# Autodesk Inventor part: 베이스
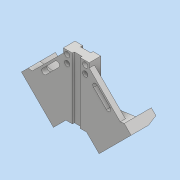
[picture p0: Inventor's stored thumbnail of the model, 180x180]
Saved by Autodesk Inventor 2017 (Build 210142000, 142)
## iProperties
Part Number: 베이스
Material: 일반
Document SubType Name: Modeling
Designer: mrc
Density: 1 g/cm^3
Appearance: 기본값
Mass: 211.682 g
Surface Area: 407.272 cm^2
Volume: 211.682 cm^3
Author: mrc
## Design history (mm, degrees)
sketch "스케치1"
  geometry: L1 (84.853, 0)-(0, -84.853); L2 (0, -84.853)-(-84.853, 0); L3 (-84.853, 0)-(0, 84.853); L4 (0, 84.853)-(84.853, 0); L5 (20, 64.853)-(-20, 64.853); L6 (35.355, -49.497)-(16.005, -30.147); L7 (16.005, -30.147)-(-16.005, -30.147); L8 (-16.005, -30.147)-(-35.355, -49.497); L9 (-24.749, -38.891)-(-74.246, 10.607); L10 (-74.246, 10.607)-(-49.497, 7.071); L11 (-49.497, 7.071)-(-20, 36.569); L12 (-20, 36.569)-(-20, 64.853); L13 (-29.698, 38.184)-(-49.497, 18.385); L14 (-32.527, 41.012)-(-52.326, 21.213); L15 (-46.669, 15.556)-(-26.87, 35.355); A1 r 4 centre (-29.698, 38.184) between (-26.87, 35.355) and (-32.527, 41.012); A2 r 4 centre (-49.497, 18.385) between (-52.326, 21.213) and (-46.669, 15.556); 3 further points
  constraints: 32 end point, 6 point on line, 4 parallel, 4 point on circle, 4 tangent, 2 centre point, 2 horizontal, 2 perpendicular, 1 coincident, 1 horizontal alignment, 1 midpoint, 1 vertical, 1 vertical alignment, 9 other
  dimensions: "d0" = 120 distance of L1.end L2.end; "d1" = 20 distance from line of L3.end L5; "d2" = 50 distance from line of L1.end L8; "d3" = 95 distance between parallel lines of L7 L5; "d4" = 15 distance between parallel lines of L2 L9; "d5" = 20 distance between parallel lines of L11 L3; "d6" = 30 distance from line of L10.end L2; "d7" = 28 distance of L13.start L13.end; "d8" = 38 distance from line of L2 L13.end; "d9" = 12 distance between parallel lines of L13 L3; "d10" = 4 radius of A2
extrude "돌출1" new body sketch "스케치1" distance "d11" = 18; taper "d12" = 0 deg
extrude "돌출2" join sketch "스케치1" distance "d13" = 24; taper "d14" = 0 deg
extrude "돌출3" cut sketch "스케치1" stored distance "d15" = 24; taper "d16" = 0 deg
extrude "돌출4" cut sketch "스케치1" distance "d17" = 10; taper "d18" = 0 deg
sketch "스케치2"
  geometry: L1 (0, 42)-(-15, 42) reference; L2 (-5, 42)-(0, 27); L3 (0, 0)-(0, 42) reference; 1 further point
  constraints: 2 end point, 2 point on line
  dimensions: "d19" = 15 vertical distance of L2.start L2.end; "d20" = 5 horizontal distance of L2.start L2.end
extrude "돌출5" cut sketch "스케치2" stored distance "d21" = 10; taper "d22" = 0 deg
sketch "스케치3"
  geometry: L1 (14, 3)-(26, 3); L2 (26, 3)-(26, 0); L3 (26, 0)-(14, 0); L4 (14, 0)-(14, 3); L5 (12, 18)-(28, 18); L6 (28, 18)-(28, 14.5); L7 (28, 14.5)-(12, 14.5); L8 (12, 14.5)-(12, 18); L9 (0, 18)-(40, 18) reference; L10 (40, 0)-(0, 0) reference; 3 further points
  constraints: 16 end point, 4 midpoint, 4 parallel, 2 horizontal, 2 perpendicular
  dimensions: "d23" = 12 distance of L2.end L3.end; "d24" = 3 distance of L1.end L2.end; "d25" = 16 distance of L6.end L7.end; "d26" = 3.5 distance of L5.end L6.end
extrude "돌출6" cut sketch "스케치3" stored distance "d27" = 10; taper "d28" = 0 deg
sketch "스케치4"
  geometry: L1 (20, 64.853)-(6, 64.853) reference; 3 further points
  constraints: 1 vertical alignment
  dimensions: "d29" = 12 distance of point (14, 46.853) point (14, 58.853); "d30" = 6 distance from line of point (14, 58.853) L1; "d31" = 14 horizontal distance of point (0, 0) point (14, 58.853)
hole "구멍1" sketch "스케치4" at (14, 58.853), (14, 46.853) diameter "d32" = 4.5; stored, may be unused: countersink angle "d36" = 90 deg, drill point angle "d38" = 118 deg; dims "d33" = 6, "d34" = 8, "d35" = 10, "d37" = 8
sketch "스케치5"
  geometry: L1 (-15, 0)-(-15, 70) reference; L2 (0, 70)-(0, 0) reference; L3 (-15, 70)-(-10, 70) reference; 2 further points
  constraints: 1 other
  dimensions: "d39" = 5 distance from line of point (-5, 35) L2; "d40" = 35 distance from line of point (-5, 35) L3
feature "엠보싱1" sketch "스케치5" dims "d0" = 120, "d1" = 20, "d2" = 50, "d3" = 95, "d4" = 15, "d5" = 20, "d6" = 30, "d7" = 28, "d8" = 38, "d9" = 12, "d10" = 4, "d41" = 0.5, "d42" = 0
sketch "스케치6"
  geometry: L1 (68.059, -9.723)-(20, -57.782); L2 (74.246, -10.607)-(20, -64.853) reference; L3 (49.497, -7.071)-(74.246, -10.607) reference; L4 (20, -64.853)-(20, -36.569) reference; 1 further point
  constraints: 2 end point, 2 point on line, 1 parallel
  dimensions: "d43" = 5 distance between parallel lines of L2 L1
extrude "돌출7" cut sketch "스케치6" stored distance "d44" = 10; taper "d45" = 0 deg
fillet "모깎기1" dims "d46" = 5
node "솔리드1"
mirror "미러1"
mirror "미러2"
mirror "미러3"
mirror "미러4"
